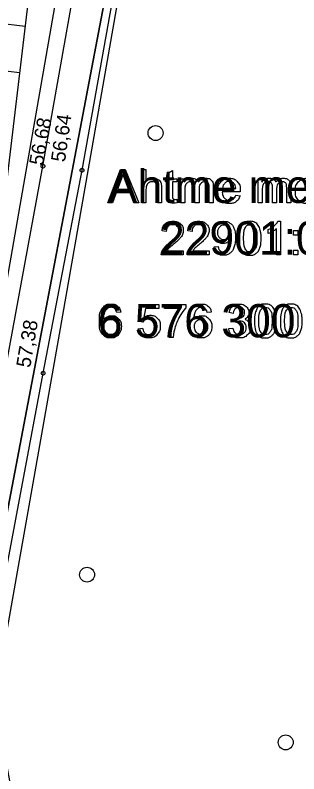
# Model space of a CAD drawing. Extents: x 700746 to 706058, y 6570320 to 6580460.
# Drawn here: x 703338.5 to 703387.1, y 6576222.3 to 6576352.4 of the extents above; entities that cross this region are included whole.
import ezdxf

# ---------------------------------------------------------------- set-up
doc = ezdxf.new("R2010")
doc.units = 0
for name, color, linetype in [('HALJASTUS', 7, 'Continuous'), ('Kaitsevöönd', 7, 'Continuous'), ('kataster', 7, 'Continuous'), ('KORGUS-EH2000', 7, 'Continuous'), ('KPOHULIIN', 7, 'Continuous'), ('Plokid', 7, 'Continuous'), ('RELJEEF', 7, 'Continuous'), ('TEE', 7, 'Continuous'), ('VORK', 7, 'Continuous'), ('VWX2_MV_PLOKK', 7, 'Continuous')]:
    doc.layers.add(name, color=color, linetype=linetype)

msp = doc.modelspace()

# ---------------------------------------------------------------- linework, layer by layer
at = {"layer": 'HALJASTUS'}
for centre in [(703362.54, 6576332.19), (703350.81, 6576256.45), (703384.84, 6576227.68)]:
    msp.add_circle(centre, 1.28, dxfattribs=at)
at = {"layer": 'Kaitsevöönd'}
msp.add_lwpolyline([(703294.41, 6577068.37), (703355.65, 6576672.76), (703381.7, 6576504.41), (703381.65, 6576500.93), (703378.17, 6576481.28), (703346.05, 6576297.71), (703328.2, 6576197.08), (703364.66, 6576062.16)], dxfattribs=at)
at = {"layer": 'kataster'}
for points in [[(703354.35, 6576320.21), (703356.55, 6576325.91), (703357.36, 6576325.91), (703359.69, 6576320.21), (703358.83, 6576320.21), (703358.17, 6576321.93), (703355.78, 6576321.93), (703355.15, 6576320.21), (703354.35, 6576320.21)], [(703360.2, 6576320.21), (703360.2, 6576325.91), (703360.9, 6576325.91), (703360.9, 6576323.86)], [(703364.76, 6576321.42), (703364.76, 6576323.8), (703364.24, 6576323.8), (703364.24, 6576324.34), (703364.76, 6576324.34), (703364.76, 6576325.36), (703365.46, 6576325.78), (703365.46, 6576324.34), (703366.16, 6576324.34), (703366.16, 6576323.8), (703365.46, 6576323.8), (703365.46, 6576321.38)], [(703356.63, 6576324.22), (703356, 6576322.54)], [(703356, 6576322.54), (703357.93, 6576322.54), (703357.34, 6576324.13)], [(703366.84, 6576320.21), (703366.84, 6576324.34), (703367.47, 6576324.34), (703367.47, 6576323.76)], [(703380.11, 6576320.21), (703380.11, 6576324.34), (703380.74, 6576324.34), (703380.74, 6576323.76)], [(703363.57, 6576322.82), (703363.57, 6576320.21), (703362.87, 6576320.21), (703362.87, 6576322.82)], [(703369.99, 6576322.61), (703369.99, 6576320.21), (703369.3, 6576320.21), (703369.3, 6576322.89)], [(703372.44, 6576323.04), (703372.44, 6576320.21), (703371.74, 6576320.21), (703371.74, 6576322.81)], [(703374, 6576322.67), (703376.31, 6576322.67)], [(703383.27, 6576322.61), (703383.27, 6576320.21), (703382.57, 6576320.21), (703382.57, 6576322.89)], [(703385.71, 6576323.04), (703385.71, 6576320.21), (703385.01, 6576320.21), (703385.01, 6576322.81)], [(703360.9, 6576322.47), (703360.9, 6576320.21), (703360.2, 6576320.21)], [(703367.54, 6576322.35), (703367.54, 6576320.21), (703366.84, 6576320.21)], [(703377.04, 6576322.09), (703373.96, 6576322.09)], [(703376.3, 6576321.54), (703377.02, 6576321.45)], [(703380.81, 6576322.35), (703380.81, 6576320.21), (703380.11, 6576320.21)], [(703366.16, 6576320.83), (703366.26, 6576320.21)], [(703383.51, 6576317.05), (703383.96, 6576317.05), (703383.96, 6576311.33)], [(703364.38, 6576315.33), (703363.66, 6576315.41)], [(703368.81, 6576315.33), (703368.09, 6576315.41)], [(703381.86, 6576314.94), (703381.86, 6576315.62)], [(703383.96, 6576311.33), (703383.26, 6576311.33), (703383.26, 6576315.79)], [(703386.15, 6576314.67), (703386.15, 6576315.46), (703386.94, 6576315.46), (703386.94, 6576314.67), (703386.15, 6576314.67)], [(703372.58, 6576312.65), (703373.25, 6576312.71)], [(703367.3, 6576312), (703367.3, 6576311.33), (703363.53, 6576311.33)], [(703364.5, 6576312), (703367.3, 6576312)], [(703371.72, 6576312), (703371.72, 6576311.33), (703367.96, 6576311.33)], [(703368.93, 6576312), (703371.72, 6576312)], [(703386.15, 6576311.33), (703386.15, 6576312.12), (703386.94, 6576312.12), (703386.94, 6576311.33), (703386.15, 6576311.33)]]:
    msp.add_lwpolyline(points, dxfattribs=at)
for points in [[(703357.34, 6576324.13), (703357.07, 6576324.85), (703356.93, 6576325.31), (703356.82, 6576324.76), (703356.63, 6576324.22)], [(703360.9, 6576323.86), (703361.39, 6576324.43), (703362.14, 6576324.43), (703362.6, 6576324.43), (703362.94, 6576324.25), (703363.27, 6576324.07), (703363.42, 6576323.75), (703363.57, 6576323.43), (703363.57, 6576322.82)], [(703367.47, 6576323.76), (703367.66, 6576324.06), (703367.98, 6576324.24), (703368.31, 6576324.43), (703368.72, 6576324.43), (703369.18, 6576324.43), (703369.47, 6576324.24), (703369.77, 6576324.05), (703369.89, 6576323.71), (703370.38, 6576324.43), (703371.16, 6576324.43), (703371.78, 6576324.43), (703372.11, 6576324.09), (703372.44, 6576323.75), (703372.44, 6576323.04)], [(703377.02, 6576321.45), (703376.85, 6576320.82), (703376.39, 6576320.47), (703375.93, 6576320.12), (703375.21, 6576320.12), (703374.3, 6576320.12), (703373.77, 6576320.67), (703373.24, 6576321.23), (703373.24, 6576322.24), (703373.24, 6576323.28), (703373.78, 6576323.85), (703374.31, 6576324.43), (703375.17, 6576324.43), (703376, 6576324.43), (703376.52, 6576323.87), (703377.05, 6576323.3), (703377.05, 6576322.28), (703377.05, 6576322.22), (703377.04, 6576322.09)], [(703376.31, 6576322.67), (703376.26, 6576323.19), (703376.04, 6576323.45), (703375.71, 6576323.86), (703375.18, 6576323.86), (703374.69, 6576323.86), (703374.37, 6576323.53), (703374.04, 6576323.21), (703374, 6576322.67)], [(703380.74, 6576323.76), (703380.93, 6576324.06), (703381.26, 6576324.24), (703381.58, 6576324.43), (703381.99, 6576324.43), (703382.45, 6576324.43), (703382.74, 6576324.24), (703383.04, 6576324.05), (703383.16, 6576323.71), (703383.65, 6576324.43), (703384.44, 6576324.43), (703385.05, 6576324.43), (703385.38, 6576324.09), (703385.71, 6576323.75), (703385.71, 6576323.04)], [(703390.3, 6576321.45), (703390.12, 6576320.82), (703389.66, 6576320.47), (703389.2, 6576320.12), (703388.48, 6576320.12), (703387.57, 6576320.12), (703387.04, 6576320.67), (703386.51, 6576321.23), (703386.51, 6576322.24), (703386.51, 6576323.28), (703387.05, 6576323.85), (703387.59, 6576324.43), (703388.44, 6576324.43), (703389.27, 6576324.43), (703389.79, 6576323.87), (703390.32, 6576323.3), (703390.32, 6576322.28), (703390.32, 6576322.22), (703390.32, 6576322.09)], [(703362.87, 6576322.82), (703362.87, 6576323.35), (703362.64, 6576323.59), (703362.41, 6576323.83), (703362, 6576323.83), (703361.68, 6576323.83), (703361.41, 6576323.66), (703361.14, 6576323.5), (703361.02, 6576323.23), (703360.9, 6576322.95), (703360.9, 6576322.47)], [(703369.3, 6576322.89), (703369.3, 6576323.36), (703369.12, 6576323.59), (703368.95, 6576323.82), (703368.56, 6576323.82), (703368.27, 6576323.82), (703368.02, 6576323.67), (703367.77, 6576323.51), (703367.65, 6576323.21), (703367.54, 6576322.91), (703367.54, 6576322.35)], [(703371.74, 6576322.81), (703371.74, 6576323.23), (703371.67, 6576323.41), (703371.61, 6576323.6), (703371.43, 6576323.71), (703371.25, 6576323.82), (703371.01, 6576323.82), (703370.57, 6576323.82), (703370.28, 6576323.53), (703369.99, 6576323.24), (703369.99, 6576322.61)], [(703382.57, 6576322.89), (703382.57, 6576323.36), (703382.4, 6576323.59), (703382.23, 6576323.82), (703381.84, 6576323.82), (703381.54, 6576323.82), (703381.29, 6576323.67), (703381.04, 6576323.51), (703380.93, 6576323.21), (703380.81, 6576322.91), (703380.81, 6576322.35)], [(703385.01, 6576322.81), (703385.01, 6576323.23), (703384.95, 6576323.41), (703384.88, 6576323.6), (703384.7, 6576323.71), (703384.52, 6576323.82), (703384.28, 6576323.82), (703383.84, 6576323.82), (703383.56, 6576323.53), (703383.27, 6576323.24), (703383.27, 6576322.61)], [(703366.26, 6576320.21), (703365.96, 6576320.15), (703365.73, 6576320.15), (703365.35, 6576320.15), (703365.14, 6576320.27), (703364.93, 6576320.39), (703364.84, 6576320.59), (703364.76, 6576320.79), (703364.76, 6576321.42)], [(703365.46, 6576321.38), (703365.46, 6576321.08), (703365.49, 6576320.99), (703365.53, 6576320.9), (703365.61, 6576320.85), (703365.7, 6576320.8), (703365.85, 6576320.8), (703365.97, 6576320.8), (703366.16, 6576320.83)], [(703373.96, 6576322.09), (703374, 6576321.41), (703374.35, 6576321.05), (703374.69, 6576320.69), (703375.21, 6576320.69), (703375.6, 6576320.69), (703375.87, 6576320.89), (703376.14, 6576321.1), (703376.3, 6576321.54)], [(703363.53, 6576311.33), (703363.52, 6576311.58), (703363.61, 6576311.82), (703363.76, 6576312.2), (703364.07, 6576312.57), (703364.39, 6576312.95), (703364.99, 6576313.44), (703365.92, 6576314.2), (703366.24, 6576314.64), (703366.57, 6576315.09), (703366.57, 6576315.49), (703366.57, 6576315.9), (703366.27, 6576316.19), (703365.97, 6576316.47), (703365.5, 6576316.47), (703364.99, 6576316.47), (703364.69, 6576316.17), (703364.38, 6576315.87), (703364.38, 6576315.33)], [(703363.66, 6576315.41), (703363.73, 6576316.21), (703364.22, 6576316.63), (703364.7, 6576317.05), (703365.51, 6576317.05), (703366.33, 6576317.05), (703366.81, 6576316.6), (703367.29, 6576316.14), (703367.29, 6576315.47), (703367.29, 6576315.13), (703367.15, 6576314.8), (703367.01, 6576314.47), (703366.68, 6576314.1), (703366.36, 6576313.74), (703365.61, 6576313.1), (703364.98, 6576312.57), (703364.8, 6576312.38), (703364.62, 6576312.19), (703364.5, 6576312)], [(703367.96, 6576311.33), (703367.95, 6576311.58), (703368.04, 6576311.82), (703368.18, 6576312.2), (703368.5, 6576312.57), (703368.82, 6576312.95), (703369.41, 6576313.44), (703370.34, 6576314.2), (703370.67, 6576314.64), (703370.99, 6576315.09), (703370.99, 6576315.49), (703370.99, 6576315.9), (703370.7, 6576316.19), (703370.4, 6576316.47), (703369.92, 6576316.47), (703369.42, 6576316.47), (703369.11, 6576316.17), (703368.81, 6576315.87), (703368.81, 6576315.33)], [(703368.09, 6576315.41), (703368.16, 6576316.21), (703368.64, 6576316.63), (703369.13, 6576317.05), (703369.94, 6576317.05), (703370.76, 6576317.05), (703371.24, 6576316.6), (703371.71, 6576316.14), (703371.71, 6576315.47), (703371.71, 6576315.13), (703371.57, 6576314.8), (703371.44, 6576314.47), (703371.11, 6576314.1), (703370.79, 6576313.74), (703370.03, 6576313.1), (703369.4, 6576312.57), (703369.23, 6576312.38), (703369.05, 6576312.19), (703368.93, 6576312)], [(703373.25, 6576312.71), (703373.34, 6576312.24), (703373.58, 6576312.02), (703373.82, 6576311.81), (703374.2, 6576311.81), (703374.52, 6576311.81), (703374.76, 6576311.96), (703375.01, 6576312.1), (703375.16, 6576312.35), (703375.31, 6576312.6), (703375.42, 6576313.02), (703375.52, 6576313.44), (703375.52, 6576313.87), (703375.52, 6576313.92), (703375.52, 6576314.01), (703375.31, 6576313.68), (703374.95, 6576313.47), (703374.58, 6576313.26), (703374.16, 6576313.26), (703373.45, 6576313.26), (703372.96, 6576313.78), (703372.47, 6576314.29), (703372.47, 6576315.13), (703372.47, 6576315.99), (703372.99, 6576316.52), (703373.5, 6576317.05), (703374.27, 6576317.05), (703374.82, 6576317.05), (703375.28, 6576316.75), (703375.74, 6576316.45), (703375.98, 6576315.9), (703376.22, 6576315.35), (703376.22, 6576314.3), (703376.22, 6576313.2), (703375.98, 6576312.56), (703375.75, 6576311.91), (703375.28, 6576311.57), (703374.81, 6576311.23), (703374.18, 6576311.23), (703373.51, 6576311.23), (703373.09, 6576311.61), (703372.66, 6576311.98), (703372.58, 6576312.65)], [(703375.44, 6576315.16), (703375.44, 6576315.77), (703375.12, 6576316.12), (703374.8, 6576316.47), (703374.35, 6576316.47), (703373.88, 6576316.47), (703373.54, 6576316.09), (703373.2, 6576315.71), (703373.2, 6576315.11), (703373.2, 6576314.56), (703373.52, 6576314.22), (703373.85, 6576313.88), (703374.33, 6576313.88), (703374.82, 6576313.88), (703375.13, 6576314.22), (703375.44, 6576314.56), (703375.44, 6576315.16)], [(703376.9, 6576314.14), (703376.9, 6576315.15), (703377.11, 6576315.77), (703377.32, 6576316.39), (703377.73, 6576316.72), (703378.14, 6576317.05), (703378.76, 6576317.05), (703379.22, 6576317.05), (703379.56, 6576316.87), (703379.91, 6576316.68), (703380.14, 6576316.33), (703380.36, 6576315.99), (703380.49, 6576315.49), (703380.62, 6576314.99), (703380.62, 6576314.14), (703380.62, 6576313.14), (703380.41, 6576312.52), (703380.2, 6576311.9), (703379.79, 6576311.57), (703379.38, 6576311.23), (703378.76, 6576311.23), (703377.94, 6576311.23), (703377.47, 6576311.82), (703376.9, 6576312.54), (703376.9, 6576314.14)], [(703377.62, 6576314.14), (703377.62, 6576312.73), (703377.95, 6576312.27), (703378.28, 6576311.81), (703378.76, 6576311.81), (703379.24, 6576311.81), (703379.57, 6576312.27), (703379.9, 6576312.74), (703379.9, 6576314.14), (703379.9, 6576315.55), (703379.57, 6576316.01), (703379.24, 6576316.47), (703378.75, 6576316.47), (703378.27, 6576316.47), (703377.98, 6576316.07), (703377.62, 6576315.54), (703377.62, 6576314.14)], [(703381.86, 6576315.62), (703382.45, 6576315.9), (703382.89, 6576316.29), (703383.33, 6576316.68), (703383.51, 6576317.05)], [(703383.26, 6576315.79), (703383.01, 6576315.55), (703382.6, 6576315.31), (703382.19, 6576315.07), (703381.86, 6576314.94)]]:
    msp.add_open_spline(points, degree=3, dxfattribs=at)
at = {"layer": 'KORGUS-EH2000'}
for centre in [(703343.25, 6576326.51), (703349.94, 6576325.8), (703343.28, 6576291)]:
    msp.add_circle(centre, 0.32, dxfattribs=at)
at = {"layer": 'KPOHULIIN'}
msp.add_lwpolyline([(703335.89, 6576129.69), (703317.61, 6576196.56), (703334.12, 6576290.28), (703354.88, 6576408.94), (703371.63, 6576502.97), (703360.78, 6576573.5), (703348.19, 6576656.26), (703310.09, 6576902.12)], dxfattribs=at)
at = {"layer": 'Plokid'}
msp.add_lwpolyline([(703294.02, 6575933.8), (703311.73, 6576015.89), (703324.97, 6576203.4), (703382.07, 6576503.63), (703406.89, 6576414.25), (703421.79, 6576214.16), (703443.8, 6575689.35), (703467.14, 6575602.46), (703308.25, 6575608.58), (703295.51, 6575829.03)], dxfattribs=at)
at = {"layer": 'RELJEEF'}
for p, q in [((703327.85, 6576351.96), (703340.18, 6576350.51)), ((703326.92, 6576344.02), (703339.24, 6576342.57))]:
    msp.add_line(p, q, dxfattribs=at)
msp.add_lwpolyline([(703294.98, 6576976.89), (703298.01, 6576952.03), (703308.39, 6576903.66), (703310.22, 6576881.63), (703320.05, 6576759.49), (703327.51, 6576726.85), (703331.13, 6576688.4), (703329.02, 6576656.14), (703332.85, 6576644.87), (703338.24, 6576624.53), (703339.69, 6576609.71), (703342.98, 6576573.75), (703350.64, 6576557.99), (703360.73, 6576522.36), (703358.27, 6576513.58), (703356.22, 6576500.08), (703348.18, 6576445.4), (703346.58, 6576371.38), (703340.93, 6576356.93), (703336.91, 6576322.74), (703327.68, 6576295.15), (703320.22, 6576257.66), (703313.5, 6576240.83), (703310.18, 6576232.92)], dxfattribs=at)
at = {"layer": 'TEE'}
for points in [[(703352.19, 6576141.74), (703333.89, 6576240.91), (703343.28, 6576291), (703349.94, 6576325.8), (703355.47, 6576356.51), (703364.51, 6576409.39), (703371.49, 6576445.79), (703377.05, 6576478.47), (703380.32, 6576501.7), (703378.7, 6576535.4), (703372.61, 6576579.28), (703366.54, 6576617.95), (703359.6, 6576660.21), (703326.86, 6576887.21), (703316.48, 6576960.36), (703310.76, 6576994.71), (703303.15, 6577040.42), (703296.06, 6577071.1), (703290.16, 6577081.59), (703186.34, 6577164.98)], [(703345.4, 6576137.9), (703327.1, 6576237.07), (703336.56, 6576290.12), (703343.25, 6576326.51), (703348.81, 6576358.13), (703358.18, 6576409.8), (703364.65, 6576448.18), (703369.91, 6576476.49), (703373.71, 6576502.52), (703371.54, 6576534.25), (703365.82, 6576575.44), (703359.75, 6576614.11), (703352.81, 6576656.37), (703320.07, 6576883.37), (703309.69, 6576956.52), (703303.97, 6576990.87), (703296.36, 6577036.58), (703289.27, 6577067.26), (703283.37, 6577077.75), (703179.55, 6577161.14)]]:
    msp.add_lwpolyline(points, dxfattribs=at)
at = {"layer": 'VORK'}
for points in [[(703360.37, 6576299.76), (703359.71, 6576299.85), (703360.26, 6576302.77), (703363.1, 6576302.77), (703363.1, 6576302.11), (703360.82, 6576302.11), (703360.52, 6576300.58)], [(703364.06, 6576302.1), (703364.06, 6576302.77), (703367.75, 6576302.77), (703367.75, 6576302.23)], [(703366.85, 6576302.1), (703364.06, 6576302.1)], [(703356.58, 6576301.45), (703355.89, 6576301.39)], [(703372.08, 6576301.45), (703371.38, 6576301.39)], [(703375.85, 6576301.27), (703375.15, 6576301.39)], [(703376.46, 6576299.85), (703376.54, 6576300.46)], [(703359.59, 6576298.64), (703360.32, 6576298.7)], [(703375.08, 6576298.66), (703375.78, 6576298.75)], [(703365.58, 6576297.15), (703364.86, 6576297.15)]]:
    msp.add_lwpolyline(points, dxfattribs=at)
for points in [[(703355.89, 6576301.39), (703355.79, 6576301.81), (703355.62, 6576302), (703355.34, 6576302.3), (703354.92, 6576302.3), (703354.59, 6576302.3), (703354.33, 6576302.11), (703354, 6576301.87), (703353.81, 6576301.41), (703353.62, 6576300.94), (703353.61, 6576300.09), (703353.86, 6576300.47), (703354.23, 6576300.66), (703354.6, 6576300.85), (703355, 6576300.85), (703355.7, 6576300.85), (703356.19, 6576300.33), (703356.68, 6576299.82), (703356.68, 6576299), (703356.68, 6576298.46), (703356.45, 6576298), (703356.22, 6576297.54), (703355.82, 6576297.3), (703355.41, 6576297.05), (703354.9, 6576297.05), (703354.02, 6576297.05), (703353.47, 6576297.7), (703352.92, 6576298.34), (703352.92, 6576299.82), (703352.92, 6576301.47), (703353.53, 6576302.22), (703354.06, 6576302.87), (703354.96, 6576302.87), (703355.64, 6576302.87), (703356.07, 6576302.49), (703356.5, 6576302.11), (703356.58, 6576301.45)], [(703364.86, 6576297.15), (703364.87, 6576297.82), (703365.12, 6576298.77), (703365.37, 6576299.73), (703365.84, 6576300.61), (703366.32, 6576301.49), (703366.85, 6576302.1)], [(703367.75, 6576302.23), (703367.2, 6576301.65), (703366.67, 6576300.69), (703366.14, 6576299.73), (703365.84, 6576298.71), (703365.63, 6576298), (703365.58, 6576297.15)], [(703371.38, 6576301.39), (703371.29, 6576301.81), (703371.12, 6576302), (703370.83, 6576302.3), (703370.41, 6576302.3), (703370.08, 6576302.3), (703369.82, 6576302.11), (703369.49, 6576301.87), (703369.3, 6576301.41), (703369.11, 6576300.94), (703369.1, 6576300.09), (703369.36, 6576300.47), (703369.72, 6576300.66), (703370.09, 6576300.85), (703370.49, 6576300.85), (703371.19, 6576300.85), (703371.68, 6576300.33), (703372.18, 6576299.82), (703372.18, 6576299), (703372.18, 6576298.46), (703371.94, 6576298), (703371.71, 6576297.54), (703371.31, 6576297.3), (703370.9, 6576297.05), (703370.39, 6576297.05), (703369.51, 6576297.05), (703368.96, 6576297.7), (703368.41, 6576298.34), (703368.41, 6576299.82), (703368.41, 6576301.47), (703369.02, 6576302.22), (703369.55, 6576302.87), (703370.46, 6576302.87), (703371.13, 6576302.87), (703371.56, 6576302.49), (703371.99, 6576302.11), (703372.08, 6576301.45)], [(703375.15, 6576301.39), (703375.28, 6576302.1), (703375.74, 6576302.48), (703376.19, 6576302.87), (703376.87, 6576302.87), (703377.33, 6576302.87), (703377.73, 6576302.67), (703378.12, 6576302.47), (703378.33, 6576302.12), (703378.54, 6576301.78), (703378.54, 6576301.39), (703378.54, 6576301.02), (703378.34, 6576300.72), (703378.14, 6576300.42), (703377.75, 6576300.24), (703378.26, 6576300.12), (703378.53, 6576299.75), (703378.81, 6576299.39), (703378.81, 6576298.84), (703378.81, 6576298.09), (703378.27, 6576297.57), (703377.73, 6576297.05), (703376.89, 6576297.05), (703376.14, 6576297.05), (703375.65, 6576297.5), (703375.15, 6576297.95), (703375.08, 6576298.66)], [(703376.54, 6576300.46), (703376.61, 6576300.46), (703376.65, 6576300.46), (703377.1, 6576300.46), (703377.46, 6576300.69), (703377.81, 6576300.92), (703377.81, 6576301.41), (703377.81, 6576301.79), (703377.55, 6576302.04), (703377.29, 6576302.3), (703376.88, 6576302.3), (703376.47, 6576302.3), (703376.2, 6576302.04), (703375.93, 6576301.78), (703375.85, 6576301.27)], [(703379.5, 6576299.96), (703379.5, 6576300.97), (703379.71, 6576301.59), (703379.92, 6576302.2), (703380.33, 6576302.54), (703380.74, 6576302.87), (703381.36, 6576302.87), (703381.82, 6576302.87), (703382.17, 6576302.69), (703382.51, 6576302.5), (703382.74, 6576302.15), (703382.96, 6576301.8), (703383.09, 6576301.31), (703383.22, 6576300.81), (703383.22, 6576299.96), (703383.22, 6576298.96), (703383.01, 6576298.34), (703382.81, 6576297.72), (703382.4, 6576297.39), (703381.99, 6576297.05), (703381.36, 6576297.05), (703380.54, 6576297.05), (703380.07, 6576297.64), (703379.5, 6576298.35), (703379.5, 6576299.96)], [(703380.23, 6576299.96), (703380.23, 6576298.55), (703380.55, 6576298.09), (703380.88, 6576297.63), (703381.36, 6576297.63), (703381.84, 6576297.63), (703382.17, 6576298.09), (703382.5, 6576298.56), (703382.5, 6576299.96), (703382.5, 6576301.37), (703382.17, 6576301.83), (703381.84, 6576302.29), (703381.35, 6576302.29), (703380.87, 6576302.29), (703380.59, 6576301.88), (703380.23, 6576301.36), (703380.23, 6576299.96)], [(703383.93, 6576299.96), (703383.93, 6576300.97), (703384.14, 6576301.59), (703384.35, 6576302.2), (703384.76, 6576302.54), (703385.17, 6576302.87), (703385.79, 6576302.87), (703386.25, 6576302.87), (703386.59, 6576302.69), (703386.94, 6576302.5), (703387.17, 6576302.15), (703387.39, 6576301.8), (703387.52, 6576301.31), (703387.65, 6576300.81), (703387.65, 6576299.96), (703387.65, 6576298.96), (703387.44, 6576298.34), (703387.23, 6576297.72), (703386.82, 6576297.39), (703386.41, 6576297.05), (703385.79, 6576297.05), (703384.97, 6576297.05), (703384.5, 6576297.64), (703383.93, 6576298.35), (703383.93, 6576299.96)], [(703384.65, 6576299.96), (703384.65, 6576298.55), (703384.98, 6576298.09), (703385.31, 6576297.63), (703385.79, 6576297.63), (703386.27, 6576297.63), (703386.6, 6576298.09), (703386.93, 6576298.56), (703386.93, 6576299.96), (703386.93, 6576301.37), (703386.6, 6576301.83), (703386.27, 6576302.29), (703385.78, 6576302.29), (703385.3, 6576302.29), (703385.01, 6576301.88), (703384.65, 6576301.36), (703384.65, 6576299.96)], [(703360.52, 6576300.58), (703361.03, 6576300.93), (703361.59, 6576300.93), (703362.34, 6576300.93), (703362.85, 6576300.41), (703363.36, 6576299.9), (703363.36, 6576299.08), (703363.36, 6576298.31), (703362.91, 6576297.75), (703362.37, 6576297.05), (703361.42, 6576297.05), (703360.64, 6576297.05), (703360.15, 6576297.49), (703359.66, 6576297.92), (703359.59, 6576298.64)], [(703353.72, 6576299), (703353.72, 6576298.63), (703353.87, 6576298.3), (703354.03, 6576297.97), (703354.3, 6576297.8), (703354.58, 6576297.63), (703354.88, 6576297.63), (703355.33, 6576297.63), (703355.64, 6576297.98), (703355.96, 6576298.34), (703355.96, 6576298.96), (703355.96, 6576299.55), (703355.65, 6576299.89), (703355.33, 6576300.23), (703354.85, 6576300.23), (703354.38, 6576300.23), (703354.05, 6576299.89), (703353.72, 6576299.55), (703353.72, 6576299)], [(703360.32, 6576298.7), (703360.4, 6576298.17), (703360.7, 6576297.9), (703360.99, 6576297.63), (703361.42, 6576297.63), (703361.93, 6576297.63), (703362.27, 6576298.01), (703362.62, 6576298.39), (703362.62, 6576299.02), (703362.62, 6576299.62), (703362.29, 6576299.97), (703361.95, 6576300.32), (703361.41, 6576300.32), (703361.06, 6576300.32), (703360.79, 6576300.16), (703360.52, 6576300.01), (703360.37, 6576299.76)], [(703369.21, 6576299), (703369.21, 6576298.63), (703369.37, 6576298.3), (703369.52, 6576297.97), (703369.79, 6576297.8), (703370.07, 6576297.63), (703370.37, 6576297.63), (703370.82, 6576297.63), (703371.14, 6576297.98), (703371.45, 6576298.34), (703371.45, 6576298.96), (703371.45, 6576299.55), (703371.14, 6576299.89), (703370.83, 6576300.23), (703370.35, 6576300.23), (703369.87, 6576300.23), (703369.54, 6576299.89), (703369.21, 6576299.55), (703369.21, 6576299)], [(703375.78, 6576298.75), (703375.9, 6576298.16), (703376.19, 6576297.89), (703376.48, 6576297.63), (703376.9, 6576297.63), (703377.39, 6576297.63), (703377.73, 6576297.97), (703378.07, 6576298.31), (703378.07, 6576298.82), (703378.07, 6576299.3), (703377.76, 6576299.62), (703377.44, 6576299.93), (703376.96, 6576299.93), (703376.76, 6576299.93), (703376.46, 6576299.85)]]:
    msp.add_open_spline(points, degree=3, dxfattribs=at)
at = {"layer": 'VWX2_MV_PLOKK'}
for points in [[(703170.54, 6577151.86), (703296.17, 6577067.83), (703382.07, 6576503.63), (703324.97, 6576203.4), (703311.73, 6576015.89), (703294.04, 6575933.77), (703293.62, 6575965.66), (703311.6, 6576228.52), (703360.09, 6576531.99), (703277.36, 6577072.83), (703231.53, 6577106.55)], [(703443.86, 6575689.39), (703467.13, 6575602.53), (703308.24, 6575608.65), (703295.44, 6575828.99), (703294.04, 6575933.77), (703311.73, 6576015.89), (703324.97, 6576203.33), (703382.07, 6576503.63), (703406.94, 6576414.24), (703421.77, 6576214.18)]]:
    msp.add_lwpolyline(points, close=True, dxfattribs=at)

# ---------------------------------------------------------------- texts
at = {"layer": 'kataster'}
for s, p in [('Ahtme metskond 25', (703354.36, 6576320.21)), ('22901:001:0239', (703363.29, 6576311.33))]:
    msp.add_text(s, height=5.7, dxfattribs=at).set_placement(p)
at = {"layer": 'KORGUS-EH2000'}
for s, rotation, p in [('56,68 ', 79.3196, (703343.25, 6576326.51)), ('56,64 ', 82.0444, (703347.02, 6576327.12)), ('57,38 ', 80.4911, (703341.06, 6576291.84))]:
    msp.add_text(s, height=2.45, rotation=rotation, dxfattribs=at).set_placement(p)
at = {"layer": 'VORK'}
msp.add_text('6 576 300', height=5.7, dxfattribs=at).set_placement((703352.62, 6576297.15))

doc.saveas('drawing.dxf')
